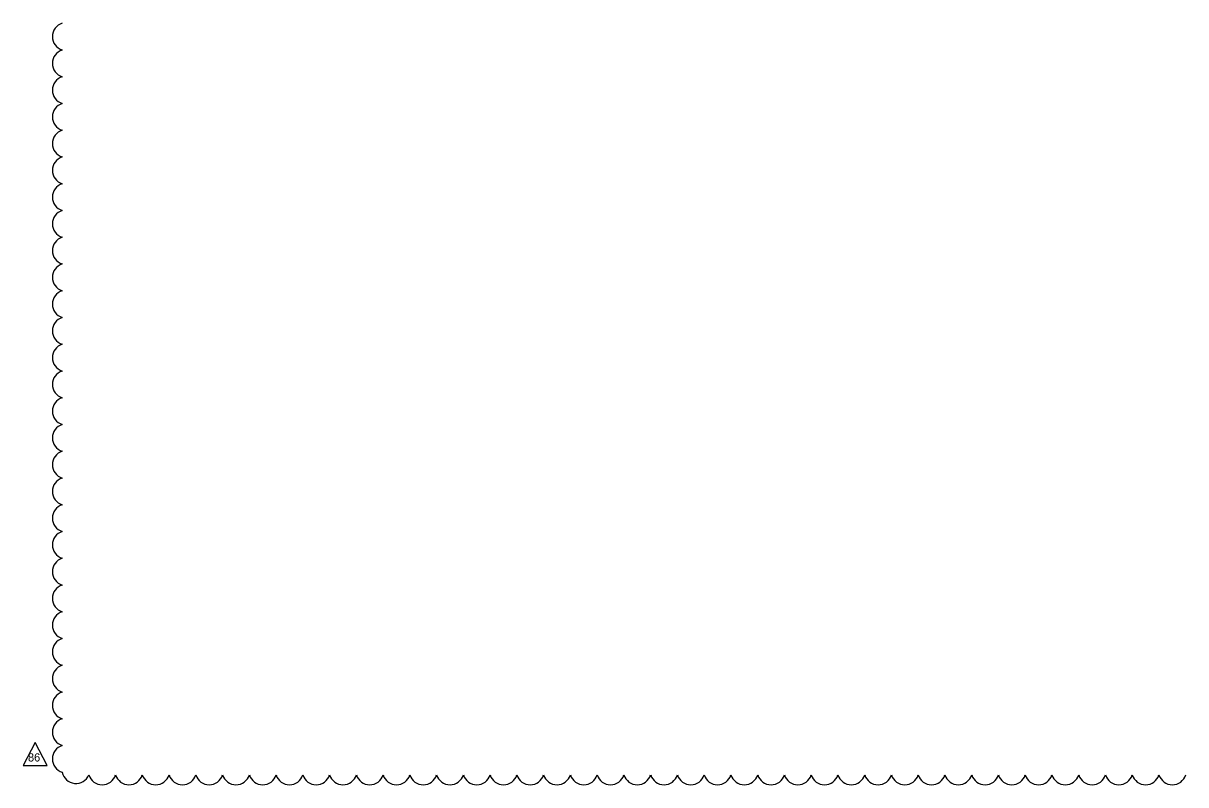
# Model space of a CAD drawing. Extents: x -811 to 10319, y -2309 to 9962.
# Drawn here: x -811.04 to -803.6, y -2213.66 to -2208.79 of the extents above; entities that cross this region are included whole.
import ezdxf

# ---------------------------------------------------------------- set-up
doc = ezdxf.new("R2010")
doc.units = 0
doc.layers.add('TextMisc', color=7, linetype='Continuous')
doc.layers.add('TextTitle', color=7, linetype='Continuous')

msp = doc.modelspace()

# ---------------------------------------------------------------- linework, layer by layer
at = {"layer": 'TextMisc'}
msp.add_lwpolyline([(-810.9581, -2213.3928), (-811.0351, -2213.5411), (-810.8811, -2213.5411)], close=True, dxfattribs=at)
at = {"layer": 'TextTitle'}
for centre, radius, start, end in [((-810.7588, -2208.8776), 0.0897, 107.5, 252.5), ((-810.7588, -2209.0488), 0.0897, 107.5, 252.5), ((-810.7588, -2209.2199), 0.0897, 107.5, 252.5), ((-810.7588, -2209.391), 0.0897, 107.5, 252.5), ((-810.7588, -2209.5621), 0.0897, 107.5, 252.5), ((-810.7588, -2209.7332), 0.0897, 107.5, 252.5), ((-810.7588, -2209.9044), 0.0897, 107.5, 252.5), ((-810.7588, -2210.0755), 0.0897, 107.5, 252.5), ((-810.7588, -2210.2466), 0.0897, 107.5, 252.5), ((-810.7588, -2210.4177), 0.0897, 107.5, 252.5), ((-810.7588, -2210.5889), 0.0897, 107.5, 252.5), ((-810.7588, -2210.76), 0.0897, 107.5, 252.5), ((-810.7588, -2210.9311), 0.0897, 107.5, 252.5), ((-810.7588, -2211.1022), 0.0897, 107.5, 252.5), ((-810.7588, -2211.2733), 0.0897, 107.5, 252.5), ((-810.7588, -2211.4445), 0.0897, 107.5, 252.5), ((-810.7588, -2211.6156), 0.0897, 107.5, 252.5), ((-810.7588, -2211.7867), 0.0897, 107.5, 252.5), ((-810.7588, -2211.9578), 0.0897, 107.5, 252.5), ((-810.7588, -2212.129), 0.0897, 107.5, 252.5), ((-810.7588, -2212.3001), 0.0897, 107.5, 252.5), ((-810.7588, -2212.4712), 0.0897, 107.5, 252.5), ((-810.7588, -2212.6423), 0.0897, 107.5, 252.5), ((-810.7588, -2212.8134), 0.0897, 107.5, 252.5), ((-810.7588, -2212.9846), 0.0897, 107.5, 252.5), ((-810.7588, -2213.1557), 0.0897, 107.5, 252.5), ((-810.7588, -2213.3268), 0.0897, 107.5, 252.5), ((-810.7588, -2213.4979), 0.0897, 107.5, 252.5), ((-810.698, -2213.5653), 0.0896, 191.74536, 336.74536), ((-810.5301, -2213.5737), 0.0897, 197.5, 342.5), ((-810.359, -2213.5737), 0.0897, 197.5, 342.5), ((-810.1879, -2213.5737), 0.0897, 197.5, 342.5), ((-810.0167, -2213.5737), 0.0897, 197.5, 342.5), ((-809.8456, -2213.5737), 0.0897, 197.5, 342.5), ((-809.6745, -2213.5737), 0.0897, 197.5, 342.5), ((-809.5034, -2213.5737), 0.0897, 197.5, 342.5), ((-809.3323, -2213.5737), 0.0897, 197.5, 342.5), ((-809.1611, -2213.5737), 0.0897, 197.5, 342.5), ((-808.99, -2213.5737), 0.0897, 197.5, 342.5), ((-808.8189, -2213.5737), 0.0897, 197.5, 342.5), ((-808.6478, -2213.5737), 0.0897, 197.5, 342.5), ((-808.4766, -2213.5737), 0.0897, 197.5, 342.5), ((-808.3055, -2213.5737), 0.0897, 197.5, 342.5), ((-808.1344, -2213.5737), 0.0897, 197.5, 342.5), ((-807.9633, -2213.5737), 0.0897, 197.5, 342.5), ((-807.7921, -2213.5737), 0.0897, 197.5, 342.5), ((-807.621, -2213.5737), 0.0897, 197.5, 342.5), ((-807.4499, -2213.5737), 0.0897, 197.5, 342.5), ((-807.2788, -2213.5737), 0.0897, 197.5, 342.5), ((-807.1077, -2213.5737), 0.0897, 197.5, 342.5), ((-806.9365, -2213.5737), 0.0897, 197.5, 342.5), ((-806.7654, -2213.5737), 0.0897, 197.5, 342.5), ((-806.5943, -2213.5737), 0.0897, 197.5, 342.5), ((-806.4232, -2213.5737), 0.0897, 197.5, 342.5), ((-806.252, -2213.5737), 0.0897, 197.5, 342.5), ((-806.0809, -2213.5737), 0.0897, 197.5, 342.5), ((-805.9098, -2213.5737), 0.0897, 197.5, 342.5), ((-805.7387, -2213.5737), 0.0897, 197.5, 342.5), ((-805.5676, -2213.5737), 0.0897, 197.5, 342.5), ((-805.3964, -2213.5737), 0.0897, 197.5, 342.5), ((-805.2253, -2213.5737), 0.0897, 197.5, 342.5), ((-805.0542, -2213.5737), 0.0897, 197.5, 342.5), ((-804.8831, -2213.5737), 0.0897, 197.5, 342.5), ((-804.7119, -2213.5737), 0.0897, 197.5, 342.5), ((-804.5408, -2213.5737), 0.0897, 197.5, 342.5), ((-804.3697, -2213.5737), 0.0897, 197.5, 342.5), ((-804.1986, -2213.5737), 0.0897, 197.5, 342.5), ((-804.0275, -2213.5737), 0.0897, 197.5, 342.5), ((-803.8563, -2213.5737), 0.0897, 197.5, 342.5), ((-803.6852, -2213.5737), 0.0897, 197.5, 342.5)]:
    msp.add_arc(centre, radius, start, end, dxfattribs=at)

# ---------------------------------------------------------------- texts
at = {"layer": 'TextMisc'}
msp.add_text('86', height=0.0525, rotation=360, dxfattribs=at).set_placement((-811.0047, -2213.5147))

doc.saveas('drawing.dxf')
